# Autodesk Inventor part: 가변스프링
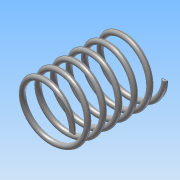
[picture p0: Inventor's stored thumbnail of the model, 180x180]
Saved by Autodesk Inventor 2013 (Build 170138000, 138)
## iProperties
Created: 2018-07
Part Number: 가변스프링
Material: 강철, 연강
Document SubType Name: Modeling
Designer: Administrator
Density: 7.86 g/cm^3
Mass: 82.807 g
Surface Area: 106.473 cm^2
Volume: 10.5352 cm^3
Author: Administrator
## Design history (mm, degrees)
sketch "스케치1"
  geometry: L1 (0, 0)-(0, 73.25); L2 (0, 0)-(22.5, 0); L3 (0, 73.25)-(22.5, 73.25); C1 r 2 at (22.5, 0)
  constraints: 6 end point, 1 centre point, 1 horizontal alignment, 1 parallel, 1 perpendicular, 1 vertical
  dimensions: "d1" = 4 diameter of C1; "d2" = 45 diameter of L2.end L1; "d3" = 22.5 distance of L1.end L3.end; "d4" = 73.25 distance of L1.start L1.end (derived)
feature "코일1" sketch "스케치1" pitch "d5" = 10; turns "d7" = 6; dims "d6" = 73.25 (= d4), "d8" = 0, angle "d9" = 90 deg, angle "d10" = 90 deg, "d11" = 0, "d12" = 0
sketch "스케치3"
  geometry: L1 (73.25, 27.5)-(0, 27.5); L2 (0, 27.5)-(0, -27.5); L3 (0, -27.5)-(73.25, -27.5); L4 (73.25, -27.5)-(73.25, 27.5); 2 further points
  constraints: 8 end point, 2 parallel, 1 coincident, 1 horizontal, 1 midpoint, 1 perpendicular
  dimensions: "d13" = 55 distance of L3.end L1.start; "d15" = 73.25 distance of L1.start L1.end (derived)
extrude "돌출1" sketch "스케치3" stored distance "d16" = 10; taper "d17" = 0 deg
node "솔리드1"
